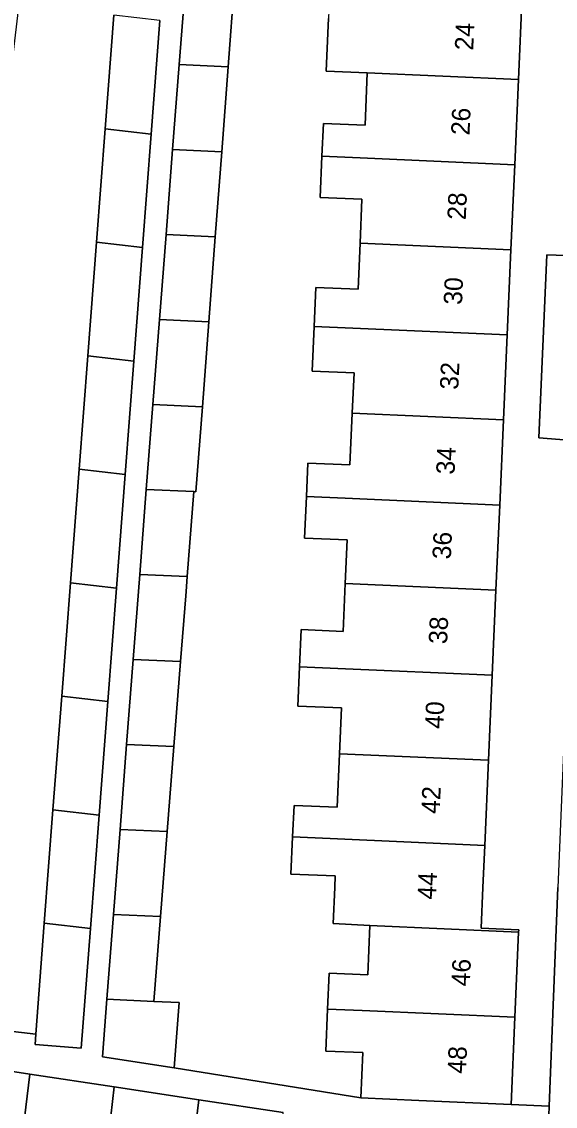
# Model space of a CAD drawing. Extents: x 162250 to 162661, y 380743 to 381606.
# Drawn here: x 162307.5 to 162336.5, y 380988.1 to 381046.9 of the extents above; entities that cross this region are included whole.
import ezdxf

# ---------------------------------------------------------------- set-up
doc = ezdxf.new("R2010")
doc.units = 0
for name, color, linetype in [('IMGEO_Erf', 7, 'Continuous'), ('IMGEO_Pand', 7, 'Continuous'), ('IMGEO_Pand_nummerreeks', 7, 'Continuous'), ('IMGEO_Voetpad_open', 7, 'Continuous')]:
    doc.layers.add(name, color=color, linetype=linetype)

msp = doc.modelspace()

# ---------------------------------------------------------------- linework, layer by layer
at = {"layer": 'IMGEO_Erf'}
for points in [[(162319.081, 381049.058), (162318.732, 381044.454), (162318.383, 381039.85), (162318.033, 381035.247), (162317.684, 381030.643), (162317.334, 381026.039), (162316.985, 381021.435), (162316.878, 381021.44), (162316.515, 381016.837), (162316.451, 381016.02), (162316.433, 381015.793), (162316.153, 381012.234), (162315.79, 381007.631), (162315.428, 381003.027), (162315.065, 380998.425), (162314.703, 380993.821), (162316.083, 380993.76), (162316.026, 380993.053), (162315.801, 380990.225), (162325.921, 380988.589), (162326.029, 380991.043), (162324.027, 380991.131), (162324.127, 380993.406), (162324.213, 380995.35), (162326.304, 380995.258), (162326.421, 380997.925), (162324.43, 380998.033), (162324.516, 381000), (162324.543, 381000.615), (162322.138, 381000.721), (162322.227, 381002.729), (162322.302, 381004.441), (162324.64, 381004.338), (162324.768, 381007.236), (162324.877, 381009.717), (162322.506, 381009.821), (162322.599, 381011.95), (162322.688, 381013.97), (162324.97, 381013.869), (162325.084, 381016.46), (162325.188, 381018.824), (162322.875, 381018.925), (162322.974, 381021.172), (162323.054, 381022.984), (162325.337, 381022.884), (162325.46, 381025.681), (162325.556, 381027.869), (162323.282, 381027.969), (162323.388, 381030.392), (162323.481, 381032.503), (162325.773, 381032.402), (162325.883, 381034.902), (162325.988, 381037.281), (162323.718, 381037.381), (162323.816, 381039.611), (162323.895, 381041.392), (162326.153, 381041.293), (162326.278, 381044.122), (162324.044, 381044.22), (162324.153, 381046.694), (162324.169, 381047.067)], [(162334.674, 381048.372), (162334.471, 381043.762), (162334.268, 381039.152), (162334.065, 381034.541), (162333.862, 381029.931), (162333.659, 381025.321), (162333.456, 381020.711), (162333.254, 381016.101), (162333.051, 381011.491), (162332.848, 381006.881), (162332.645, 381002.27), (162332.545, 381000), (162332.448, 380997.793), (162334.488, 380997.703), (162334.482, 380997.57), (162334.279, 380992.96), (162334.071, 380988.231), (162336.141, 380988.151), (162336.6, 381000)], [(162307.374, 381047.844), (162306.668, 381041.722), (162304.121, 381042.015), (162303.415, 381035.893), (162302.71, 381029.771), (162302.005, 381023.65), (162301.299, 381017.528), (162300.593, 381011.406), (162299.888, 381005.284), (162299.279, 381000), (162299.182, 380999.162), (162298.492, 380993.175), (162308.303, 380992.045), (162308.763, 380998.057), (162309.234, 381004.207), (162309.705, 381010.356), (162310.176, 381016.505), (162310.647, 381022.654), (162311.118, 381028.802), (162311.589, 381034.952), (162312.06, 381041.1), (162312.531, 381047.249)], [(162337.62, 381024.184), (162335.584, 381024.354), (162336.016, 381034.263), (162338.044, 381034.203)]]:
    msp.add_lwpolyline(points, dxfattribs=at)
at = {"layer": 'IMGEO_Pand'}
for points in [[(162319.081, 381049.058), (162316.43, 381049.175), (162316.074, 381044.571), (162318.732, 381044.454)], [(162334.674, 381048.372), (162326.3, 381048.74), (162324.247, 381048.83), (162324.169, 381047.067), (162324.153, 381046.694), (162324.044, 381044.22), (162326.278, 381044.122), (162334.471, 381043.762)], [(162314.561, 381040.812), (162315.032, 381046.961), (162312.531, 381047.249), (162312.06, 381041.1)], [(162316.074, 381044.571), (162315.718, 381039.968), (162318.383, 381039.85), (162318.732, 381044.454)], [(162326.278, 381044.122), (162326.153, 381041.293), (162323.895, 381041.392), (162323.816, 381039.611), (162325.894, 381039.52), (162334.268, 381039.152), (162334.471, 381043.762)], [(162314.561, 381040.812), (162312.06, 381041.1), (162311.589, 381034.952), (162314.09, 381034.664)], [(162318.033, 381035.247), (162318.383, 381039.85), (162315.718, 381039.968), (162315.362, 381035.364)], [(162325.883, 381034.902), (162334.065, 381034.541), (162334.268, 381039.152), (162325.894, 381039.52), (162323.816, 381039.611), (162323.718, 381037.381), (162325.988, 381037.281)], [(162317.684, 381030.643), (162318.033, 381035.247), (162315.362, 381035.364), (162315.006, 381030.761)], [(162314.09, 381034.664), (162311.589, 381034.952), (162311.118, 381028.802), (162313.619, 381028.514)], [(162323.388, 381030.392), (162325.488, 381030.3), (162333.862, 381029.931), (162334.065, 381034.541), (162325.883, 381034.902), (162325.773, 381032.402), (162323.481, 381032.503)], [(162317.684, 381030.643), (162315.006, 381030.761), (162314.65, 381026.157), (162317.334, 381026.039)], [(162323.388, 381030.392), (162323.282, 381027.969), (162325.556, 381027.869), (162325.46, 381025.681), (162333.659, 381025.321), (162333.862, 381029.931), (162325.488, 381030.3)], [(162310.647, 381022.654), (162313.148, 381022.366), (162313.619, 381028.514), (162311.118, 381028.802)], [(162317.334, 381026.039), (162314.65, 381026.157), (162314.294, 381021.554), (162316.878, 381021.44), (162316.985, 381021.435)], [(162333.456, 381020.711), (162333.659, 381025.321), (162325.46, 381025.681), (162325.337, 381022.884), (162323.054, 381022.984), (162322.974, 381021.172), (162325.081, 381021.079)], [(162310.647, 381022.654), (162310.176, 381016.505), (162312.677, 381016.217), (162313.148, 381022.366)], [(162316.878, 381021.44), (162314.294, 381021.554), (162313.938, 381016.95), (162316.515, 381016.837)], [(162333.254, 381016.101), (162333.456, 381020.711), (162325.081, 381021.079), (162322.974, 381021.172), (162322.875, 381018.925), (162325.188, 381018.824), (162325.084, 381016.46)], [(162316.515, 381016.837), (162313.938, 381016.95), (162313.582, 381012.347), (162316.153, 381012.234), (162316.433, 381015.793), (162316.451, 381016.02)], [(162312.677, 381016.217), (162310.176, 381016.505), (162309.705, 381010.356), (162312.206, 381010.067)], [(162322.599, 381011.95), (162324.674, 381011.859), (162333.051, 381011.491), (162333.254, 381016.101), (162325.084, 381016.46), (162324.97, 381013.869), (162322.688, 381013.97)], [(162313.226, 381007.744), (162315.79, 381007.631), (162316.153, 381012.234), (162313.582, 381012.347)], [(162322.599, 381011.95), (162322.506, 381009.821), (162324.877, 381009.717), (162324.768, 381007.236), (162332.848, 381006.881), (162333.051, 381011.491), (162324.674, 381011.859)], [(162309.234, 381004.207), (162311.735, 381003.918), (162312.206, 381010.067), (162309.705, 381010.356)], [(162313.226, 381007.744), (162312.87, 381003.14), (162315.428, 381003.027), (162315.79, 381007.631)], [(162322.227, 381002.729), (162324.267, 381002.639), (162332.645, 381002.27), (162332.848, 381006.881), (162324.768, 381007.236), (162324.64, 381004.338), (162322.302, 381004.441)], [(162309.234, 381004.207), (162308.763, 380998.057), (162311.264, 380997.769), (162311.735, 381003.918)], [(162315.065, 380998.425), (162315.428, 381003.027), (162312.87, 381003.14), (162312.515, 380998.537)], [(162326.421, 380997.925), (162334.482, 380997.57), (162334.488, 380997.703), (162332.448, 380997.793), (162332.545, 381000), (162332.645, 381002.27), (162324.267, 381002.639), (162322.227, 381002.729), (162322.138, 381000.721), (162324.543, 381000.615), (162324.516, 381000), (162324.43, 380998.033)], [(162311.264, 380997.769), (162308.763, 380998.057), (162308.303, 380992.045), (162308.26, 380991.48), (162310.768, 380991.288)], [(162314.703, 380993.821), (162315.065, 380998.425), (162312.515, 380998.537), (162312.159, 380993.933)], [(162326.421, 380997.925), (162326.304, 380995.258), (162324.213, 380995.35), (162324.127, 380993.406), (162326.001, 380993.324), (162334.279, 380992.96), (162334.482, 380997.57)], [(162314.703, 380993.821), (162312.159, 380993.933), (162311.918, 380990.819), (162315.801, 380990.225), (162316.026, 380993.053), (162316.083, 380993.76)], [(162324.127, 380993.406), (162324.027, 380991.131), (162326.029, 380991.043), (162325.921, 380988.589), (162329.076, 380988.45), (162334.071, 380988.231), (162334.279, 380992.96), (162326.001, 380993.324)], [(162307.698, 380987.503), (162307.978, 380989.884), (162303.395, 380990.582), (162303.115, 380988.2)], [(162312.278, 380986.806), (162312.557, 380989.187), (162307.978, 380989.884), (162307.698, 380987.503)], [(162312.278, 380986.806), (162316.858, 380986.109), (162317.138, 380988.49), (162312.557, 380989.187)], [(162321.721, 380987.792), (162317.138, 380988.49), (162316.858, 380986.109), (162321.44, 380985.411)]]:
    msp.add_lwpolyline(points, close=True, dxfattribs=at)
at = {"layer": 'IMGEO_Voetpad_open'}
for points in [[(162341.565, 381113.994), (162340.767, 381095.921), (162340.701, 381094.418), (162338.044, 381034.203), (162336.016, 381034.263), (162335.584, 381024.354), (162337.62, 381024.184), (162336.6, 381000), (162336.141, 380988.151), (162336.042, 380985.614), (162335.689, 380976.508), (162335.219, 380968.294), (162338.032, 380967.948)], [(162336.042, 380985.614), (162336.141, 380988.151), (162334.071, 380988.231), (162329.076, 380988.45), (162325.921, 380988.589), (162315.801, 380990.225), (162311.918, 380990.819), (162312.159, 380993.933), (162312.515, 380998.537), (162312.87, 381003.14), (162313.226, 381007.744), (162313.582, 381012.347), (162313.938, 381016.95), (162314.294, 381021.554), (162314.65, 381026.157), (162315.006, 381030.761), (162315.362, 381035.364), (162315.718, 381039.968), (162316.074, 381044.571), (162316.43, 381049.175)], [(162315.032, 381046.961), (162314.561, 381040.812), (162314.09, 381034.664), (162313.619, 381028.514), (162313.148, 381022.366), (162312.677, 381016.217), (162312.206, 381010.067), (162311.735, 381003.918), (162311.264, 380997.769), (162310.768, 380991.288), (162308.26, 380991.48), (162308.303, 380992.045), (162298.492, 380993.175)], [(162303.395, 380990.582), (162307.978, 380989.884), (162312.557, 380989.187), (162317.138, 380988.49), (162321.721, 380987.792)]]:
    msp.add_lwpolyline(points, dxfattribs=at)

# ---------------------------------------------------------------- texts
at = {"layer": 'IMGEO_Pand_nummerreeks'}
for s, rotation, p in [('24', 87.4792, (162332.017, 381045.326)), ('26', 87.48029, (162331.815, 381040.732)), ('28', 87.48029, (162331.613, 381036.14)), ('30', 87.48029, (162331.41, 381031.545)), ('32', 87.48029, (162331.208, 381026.944)), ('34', 87.48029, (162331.006, 381022.352)), ('36', 87.48029, (162330.804, 381017.756)), ('38', 87.48029, (162330.602, 381013.164)), ('40', 87.48029, (162330.399, 381008.569)), ('42', 87.48029, (162330.197, 381003.968)), ('44', 87.48046, (162329.993, 380999.318)), ('46', 87.47921, (162331.83, 380994.621)), ('48', 87.47921, (162331.621, 380989.888))]:
    msp.add_text(s, height=1, rotation=rotation, dxfattribs=at).set_placement(p)

doc.saveas('drawing.dxf')
